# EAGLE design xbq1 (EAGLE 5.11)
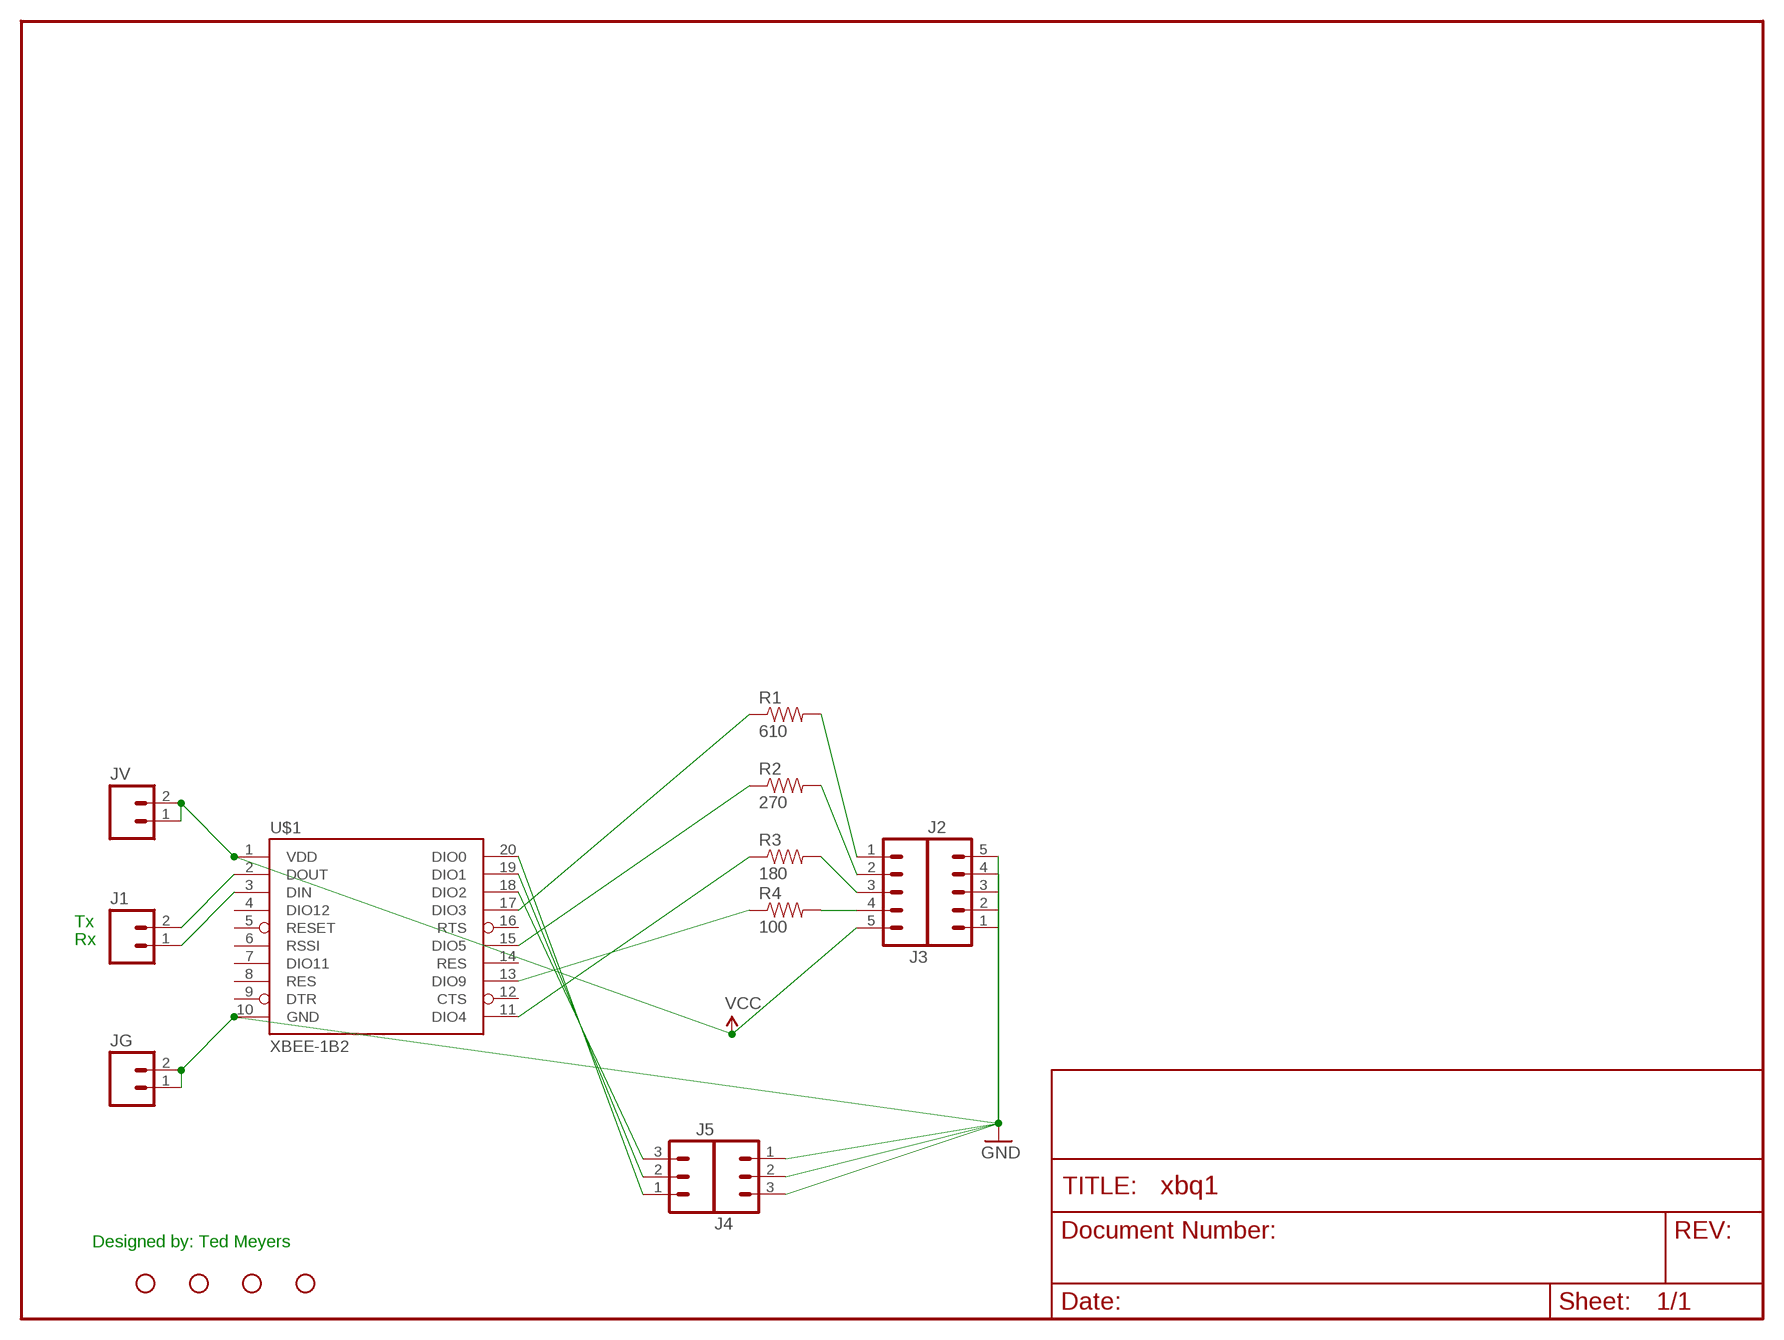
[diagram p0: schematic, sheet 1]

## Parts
J1  M02PTH  [1X02]
J2  M05PTH  [1X05]
J3  M05PTH  [1X05]
J4  M03PTH  [1X03]
J5  M03PTH  [1X03]
JG  M02PTH  [1X02]
JP6  STAND-OFF  [STAND-OFF]
JP7  STAND-OFF  [STAND-OFF]
JP8  STAND-OFF  [STAND-OFF]
JP9  STAND-OFF  [STAND-OFF]
JV  M02PTH  [1X02]
R1  610  RESISTORPTH-1/4W  [AXIAL-0.4]
R2  270  RESISTORPTH-1/4W  [AXIAL-0.4]
R3  180  RESISTORPTH-1/4W  [AXIAL-0.4]
R4  100  RESISTORPTH-1/4W  [AXIAL-0.4]
U$1  XBEE-1B2  [XBEE-SILK]

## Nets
GND: J2.1 J2.2 J2.3 J2.4 J2.5 J4.1 J4.2 J4.3 JG.1 JG.2 U$1.10(GND)
N$1: R1.P$1 U$1.17(DIO3)
N$2: R2.P$1 U$1.15(DIO5)
N$3: R3.P$1 U$1.11(DIO4)
N$4: J3.1 R1.P$2
N$5: J3.2 R2.P$2
N$6: J3.3 R3.P$2
N$7: J3.4 R4.P$2
N$8: J1.2 U$1.2(DOUT)
N$9: J1.1 U$1.3(DIN)
N$10: J5.2 U$1.19(DIO1)
N$11: J5.1 U$1.20(DIO0)
N$12: J5.3 U$1.18(DIO2)
N$13: R4.P$1 U$1.13(DIO9)
VCC: J3.5 JV.1 JV.2 U$1.1(VDD)
Unconnected: U$1.4(DIO12) U$1.5(RESET) U$1.6(RSSI) U$1.7(DIO11) U$1.8(RES) U$1.9(DTR) U$1.12(CTS) U$1.14(RES) U$1.16(RTS)

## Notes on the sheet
- Tx
- Rx
- Designed by: Ted Meyers

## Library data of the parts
J1 JG JV = SparkFun:M02: Header 2
J2 J3 = SparkFun:M05: Header 5 Standard 5-pin 0.1" header. Use with straight break away headers (SKU : PRT-00116), right angle break away headers (PRT-00553), swiss pins (PRT-00743), machine pins (PRT-00117), and female headers (PRT-00115). Molex polarized connector foot print use with SKU : PRT-08230 with associated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
J4 J5 = SparkFun:M03: Header 3 Standard 3-pin 0.1" header. Use with straight break away headers (SKU : PRT-00116), right angle break away headers (PRT-00553), swiss pins (PRT-00743), machine pins (PRT-00117), and female headers (PRT-00115). Molex polarized connector foot print use with SKU : PRT-08232 with associated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
JP6-JP9 = SparkFun:STAND-OFF: Stand Off
R1-R4 = SparkFun:RESISTOR: Resistor
U$1 = SparkFun:XBEE-1

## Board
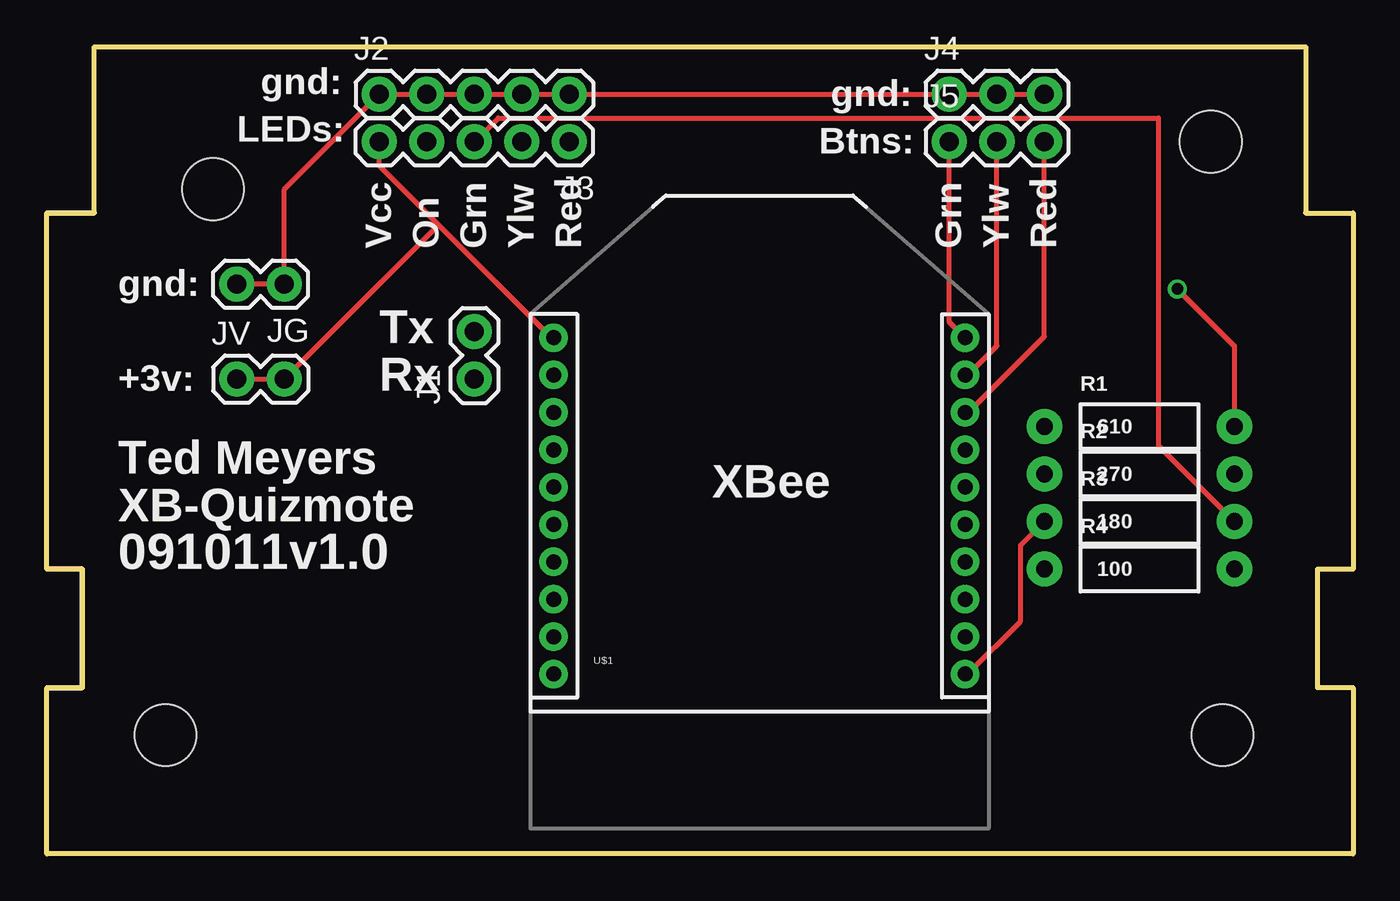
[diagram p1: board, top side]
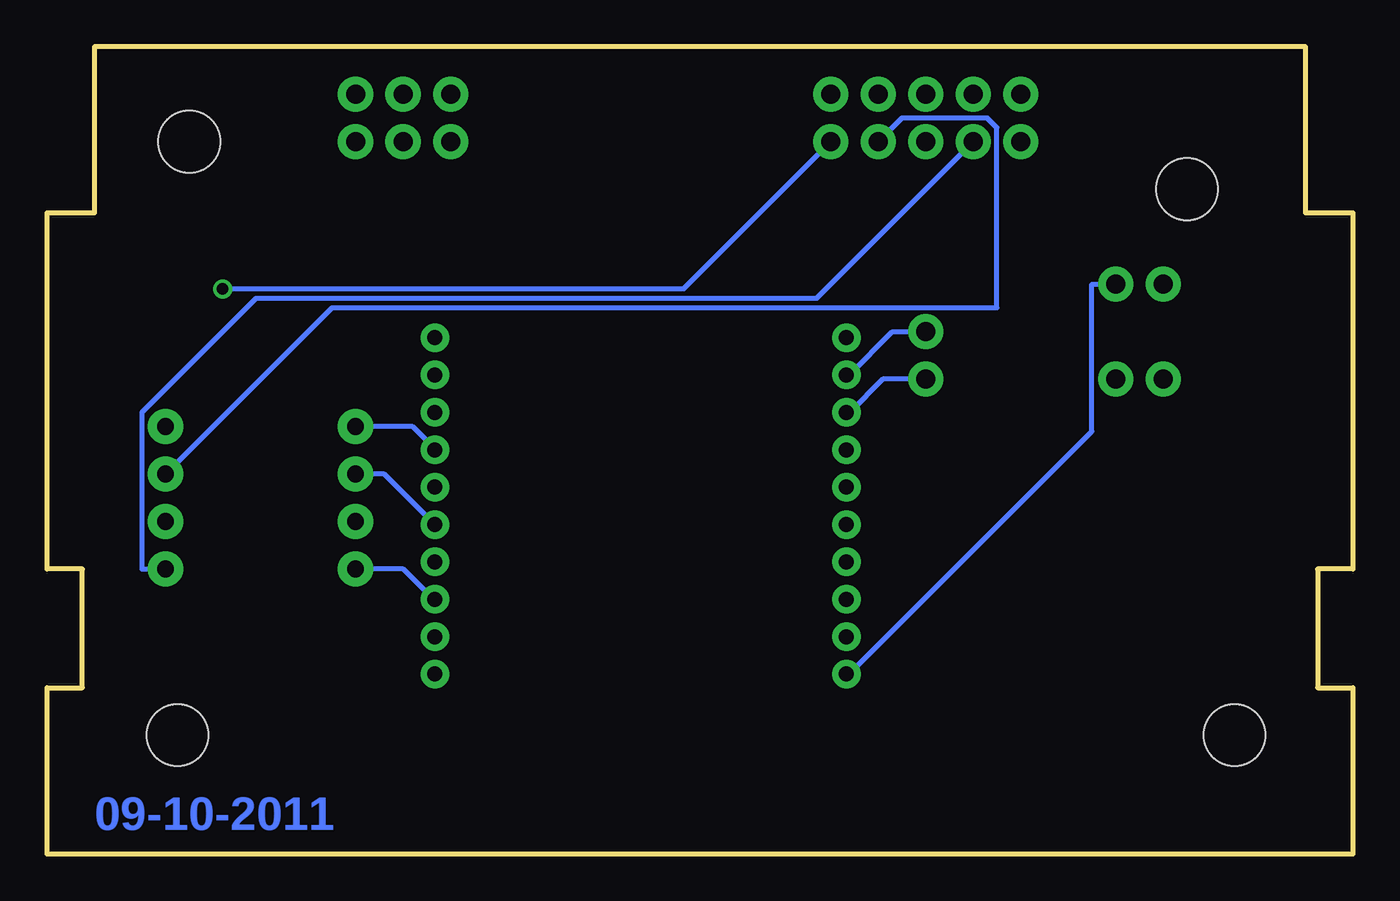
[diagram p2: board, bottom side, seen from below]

Size 69.85 x 43.18 mm. Coordinates in mm from the lower left corner, seen from the top.
Outline: 0,0 0,8.89 1.91,8.89 1.91,15.24 0,15.24 0,34.29 2.54,34.29 2.54,43.18 67.31,43.18 67.31,34.29 69.85,34.29 69.85,15.24 67.94,15.24 67.94,8.89 69.85,8.89 69.85,0 0,0
Copper layers (1*16): Top 0.035mm / dielectric 1.5mm / Bottom 0.035mm
Design rules "default": minimum track width 10mil, minimum drill 24mil, track to track 8mil, track to pad 8mil, pad to pad 8mil, via to via 8mil, smd to smd 8mil, copper to edge 40mil, drill to drill 8mil, minimum pad ring 10mil, minimum via ring 8mil, stop-mask expansion 4mil, vias tented up to drill 0mil, thermal gap 10mil

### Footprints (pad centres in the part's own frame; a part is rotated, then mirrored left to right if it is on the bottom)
1X02 = drill 1.016 pad 1.88 round: 1 0,0; 2 2.54,0
1X05 = drill 1.016 pad 1.88 round: 1 0,0; 2 2.54,0; 3 5.08,0; 4 7.62,0; 5 10.16,0
1X03 = drill 1.016 pad 1.88 round: 1 0,0; 2 2.54,0; 3 5.08,0
STAND-OFF = hole 3.302: 0,0
AXIAL-0.4 = drill 0.9 pad 1.88 round: P$1 -5.08,0; P$2 5.08,0
XBEE-SILK = drill 0.8 pad 1.524 round: 1 -11,20; 2 -11,18; 3 -11,16; 4 -11,14; 5 -11,12; 6 -11,10; 7 -11,8; 8 -11,6; 9 -11,4; 10 -11,2; 11 11,2; 12 11,4; 13 11,6; 14 11,8; 15 11,10; 16 11,12; 17 11,14; 18 11,16; 19 11,18; 20 11,20

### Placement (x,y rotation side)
J1  22.86,25.4 90 top
J2  17.78,40.64 0 top
J3  27.94,38.1 180 top
J4  48.26,40.64 0 top
J5  48.26,38.1 0 top
JG  12.7,30.48 180 top
JP6  6.35,6.35 0 top
JP7  8.89,35.56 0 top
JP8  62.23,38.1 0 top
JP9  62.87,6.35 0 top
JV  10.16,25.4 0 top
R1  58.42,22.86 0 top
R2  58.42,20.32 0 top
R3  58.42,17.78 0 top
R4  58.42,15.24 0 top
U$1  38.1,7.62 0 top

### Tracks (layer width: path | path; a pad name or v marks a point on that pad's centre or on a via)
GND
  Top 0.254: J4.3 J4.2 J4.1 J2.5 J2.4 J2.3 J2.2 J2.1 12.7,35.56 JG.1 JG.2
  Bottom 0.254: JG.1 13.97,30.48 13.97,22.61 26.92,9.65 U$1.10
N$1
  Bottom 0.254: R1.P$1 50.29,22.86 49.28,21.84 U$1.17
N$2
  Bottom 0.254: R2.P$1 51.82,20.32 49.28,17.78 U$1.15
N$3
  Top 0.254: R3.P$1 52.07,16.51 52.07,12.45 49.28,9.65 U$1.11
N$4  (via drill 0.61)
  Top 0.254: v60.45,30.23 63.5,27.18 R1.P$2
  Bottom 0.254: J3.1 35.81,30.23 v60.45,30.23
N$5
  Bottom 0.254: J3.2 24.13,39.37 19.56,39.37 19.05,38.86 19.05,29.21 54.61,29.21 R2.P$2
N$6
  Top 0.254: J3.3 24.13,39.37 59.44,39.37 59.44,21.84 R3.P$2
N$7
  Bottom 0.254: J3.4 28.7,29.72 58.67,29.72 64.77,23.62 64.77,15.24 R4.P$2
N$8
  Bottom 0.254: J1.2 24.64,27.94 26.92,25.65 U$1.2
N$9
  Bottom 0.254: J1.1 25.15,25.4 26.92,23.62 U$1.3
N$10
  Top 0.254: J5.2 50.8,27.18 49.28,25.65 U$1.19
N$11
  Top 0.254: J5.1 48.26,28.45 49.02,27.69 U$1.20
N$12
  Top 0.254: J5.3 53.34,27.69 49.28,23.62 U$1.18
N$13
  Bottom 0.254: R4.P$1 50.8,15.24 49.28,13.72 U$1.13
VCC
  Top 0.254: JV.1 JV.2 20.83,33.53 20.83,33.78 | 20.83,33.78 17.78,36.83 J3.5 | 20.83,33.78 26.92,27.69 U$1.1

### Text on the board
Bottom: 09-10-2011
tPlace: gnd: | gnd: | LEDs: | Btns: | Vcc | On | Grn | Ylw | Red | Grn | Ylw | Red | gnd: | Tx | +3v: | Rx | Ted Meyers | XBee | XB-Quizmote | 091011v1.0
